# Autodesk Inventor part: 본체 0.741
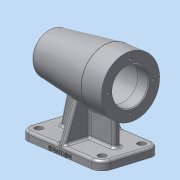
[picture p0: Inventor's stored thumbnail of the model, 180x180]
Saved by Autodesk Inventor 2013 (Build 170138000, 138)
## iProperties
Created: 2018-09
Part Number: 본체 0.741
Material: 알루미늄 6061
Document SubType Name: Modeling
Designer: Administrator
Mass: 734.473 g
Surface Area: 668.157 cm^2
Volume: 271.023 cm^3
Density: 2.71 g/cm^3
Author: Administrator
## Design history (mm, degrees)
sketch "스케치1"
  geometry: L1 (-56, 35)-(56, 35); L2 (56, 35)-(56, -35); L3 (56, -35)-(-56, -35); L4 (-56, -35)-(-56, 35); L5 (-56, 35)-(56, -35); L6 (56, 35)-(-56, -35); 1 further point
  constraints: 12 end point, 2 midpoint, 2 parallel, 1 horizontal, 1 perpendicular
  dimensions: "d0" = 112 distance of L2.end L3.end; "d1" = 70 distance of L1.end L2.end
extrude "돌출1" new body sketch "스케치1" distance "d2" = 10; taper "d3" = 0 deg
sketch "스케치2"
  geometry: L1 (-56, 0)-(56, 0) reference; L2 (-56, 74)-(56, 74); L3 (56, 74)-(56, 108); L4 (56, 108)-(28, 108); L5 (28, 108)-(-52.27, 98.144); A1 r 80 centre (24, 74) between (-52.27, 98.144) and (-56, 74); 1 further point
  constraints: 8 end point, 2 perpendicular, 2 point on circle, 1 centre point, 1 parallel, 1 point on line, 1 vertical alignment
  dimensions: "d4" = 112 distance of L2.start L2.end; "d6" = 74 distance between parallel lines of L1 L2; "d7" = 80 radius of A1; "d8" = 68 diameter of L4 L2; "d9" = 28 distance of L3.end L4.end; "d10" = 7 deg angle of L5 L4
revolve "회전1" sketch "스케치2" stored, may be unused: angle "d11" = 90 deg
sketch "스케치3"
  geometry: L1 (56, 40)-(56, 108) reference; L2 (-56, 74)-(56, 74); L3 (56, 95)-(41, 95); L4 (41, 95)-(41, 98); L5 (41, 98)-(-13, 98); L6 (-13, 98)-(-13, 95); L7 (-13, 95)-(-25, 95); L8 (-25, 95)-(-25, 91.5); L9 (-25, 91.5)-(-43, 91.5); L10 (-43, 91.5)-(-43, 90); L11 (-43, 90)-(-47, 90); L12 (-47, 90)-(-47, 84.5); L13 (-47, 84.5)-(-50, 84.5); L14 (-50, 84.5)-(-50, 74); L15 (56, 95)-(56, 74); A1 r 80 centre (24, 74) between (-52.27, 98.144) and (-52.27, 49.856) reference; 1 further point
  constraints: 28 end point, 10 parallel, 2 perpendicular, 2 point on line, 1 collinear, 1 midpoint, 1 point on circle
  dimensions: "d12" = 42 diameter of L3 L2; "d14" = 48 diameter of L5 L2; "d15" = 42 diameter of L7 L2; "d16" = 35 diameter of L9 L2; "d17" = 32 diameter of L11 L2; "d18" = 21 diameter of L13 L2; "d19" = 15 distance between parallel lines of L1 L4; "d20" = 54 distance between parallel lines of L4 L6; "d21" = 12 distance of L6.end L7.end; "d22" = 18 distance of L8.end L9.end; "d23" = 4 distance between parallel lines of L10 L12; "d24" = 3 distance between parallel lines of L12 L14
revolve "회전2" sketch "스케치3" stored, may be unused: angle "d25" = 90 deg
fillet "모깎기1" dims "d30" = 3
fillet "모깎기2" dims "d31" = 3
fillet "모깎기3" dims "d32" = 3
fillet "모깎기4" dims "d33" = 0.3
chamfer "모따기1" distance "d34" = 1; stored, may be unused: second distance "d35" = 2, angle "d36" = 45 deg
sketch "스케치9"
  geometry: L1 (56, 10)-(56, 0) reference; L2 (56, 0)-(-56, 0) reference; L3 (-56, 0)-(-56, 10) reference; L4 (-56, 10)-(56, 10) reference; L5 (-50.331, 98.382)-(27.818, 107.978) reference; L6 (28.183, 108)-(56, 108) reference; L7 (56, 108)-(56, 96) reference; L8 (56, 96)-(55, 95) reference; L9 (55, 95)-(41, 95) reference; L10 (38, 98)-(-10, 98) reference; L11 (-13, 95)-(-24.7, 95) reference; L12 (-25, 94.7)-(-25, 91.5) reference; L13 (-25, 91.5)-(-42.7, 91.5) reference; L14 (-43, 91.2)-(-43, 90) reference; L15 (-43, 90)-(-46.7, 90) reference; L16 (-47, 89.7)-(-47, 84.5) reference; L17 (-50, 81.5)-(-50, 66.5) reference; L18 (-47, 63.5)-(-47, 58.3) reference; L19 (-46.7, 58)-(-43, 58) reference; L20 (-43, 58)-(-43, 56.8) reference; L21 (-42.7, 56.5)-(-25, 56.5) reference; L22 (-25, 56.5)-(-25, 53.3) reference; L23 (-24.7, 53)-(-13, 53) reference; L24 (-10, 50)-(38, 50) reference; L25 (41, 53)-(55, 53) reference; L26 (55, 53)-(56, 52) reference; L27 (56, 52)-(56, 40) reference; L28 (56, 40)-(28.183, 40) reference; L29 (27.818, 40.022)-(-50.331, 49.618) reference; L30 (-28.115, 46.89)-(-38, 10); L31 (38, 10)-(38, 40); L32 (-38, 10)-(38, 10); A1 r 3 centre (-49.965, 95.405) between (-50.331, 98.382) and (-52.847, 96.238) reference; A2 r 3 centre (28.183, 105) between (28.183, 108) and (27.818, 107.978) reference; A3 r 3 centre (38, 95) between (41, 95) and (38, 98) reference; A4 r 3 centre (-10, 95) between (-10, 98) and (-13, 95) reference; A5 r 0.3 centre (-24.7, 94.7) between (-24.7, 95) and (-25, 94.7) reference; A6 r 0.3 centre (-42.7, 91.2) between (-42.7, 91.5) and (-43, 91.2) reference; A7 r 0.3 centre (-46.7, 89.7) between (-46.7, 90) and (-47, 89.7) reference; A8 r 3 centre (-47, 81.5) between (-47, 84.5) and (-50, 81.5) reference; A9 r 3 centre (-47, 66.5) between (-50, 66.5) and (-47, 63.5) reference; A10 r 0.3 centre (-46.7, 58.3) between (-47, 58.3) and (-46.7, 58) reference; A11 r 0.3 centre (-42.7, 56.8) between (-43, 56.8) and (-42.7, 56.5) reference; A12 r 0.3 centre (-24.7, 53.3) between (-25, 53.3) and (-24.7, 53) reference; A13 r 3 centre (-10, 53) between (-13, 53) and (-10, 50) reference; A14 r 3 centre (38, 53) between (38, 50) and (41, 53) reference; A15 r 3 centre (28.183, 43) between (27.818, 40.022) and (28.183, 40) reference; A16 r 3 centre (-49.965, 52.595) between (-52.847, 51.762) and (-50.331, 49.618) reference; A17 r 80 centre (24, 74) between (-52.847, 96.238) and (-52.847, 51.762) reference; 1 further point
  constraints: 6 end point, 4 point on line, 1 collinear, 1 perpendicular
  dimensions: "d40" = 18 distance between parallel lines of L1 L31; "d41" = 18 distance of L3.end L30.end; "d42" = 105 deg angle of L4 L30
feature "리브1" sketch "스케치9" dims "d43" = 1, "d44" = 8, "d45" = 0, "d46" = 0, "d47" = 1, "d48" = 1
fillet "모깎기6" dims "d57" = 12
fillet "모깎기8" dims "d59" = 3
sketch "스케치11"
  geometry: L1 (100, 0)-(100, 10) reference; 3 further points
  constraints: 1 other
  dimensions: "d63" = 56 distance from line of L1 point (44, 3); "d64" = 3 vertical distance of L1.start point (44, 3)
feature "엠보싱1" sketch "스케치11" dims "d0" = 112, "d1" = 70, "d65" = 0.5, "d66" = 0
sketch "스케치12"
  geometry: C1 r 34 at (0, 0) reference; 2 further points
  constraints: 1 vertical alignment
  dimensions: "d67" = 26 distance of C1.centre point (0, 26)
hole "구멍1" sketch "스케치12" at (0, 26) diameter "d68" = 3.242; stored, may be unused: countersink angle "d72" = 90 deg, drill point angle "d74" = 118 deg; dims "d69" = 8, "d70" = 4, "d71" = 2, "d73" = 11
sketch "스케치13"
  geometry: L1 (56, 23)-(56, -23) reference; L2 (44, -35)-(-44, -35) reference; L3 (-56, -23)-(-56, 23) reference; L4 (-44, 35)-(44, 35) reference; A1 r 12 centre (44, 23) between (56, 23) and (44, 35) reference; A2 r 12 centre (44, -23) between (44, -35) and (56, -23) reference; A3 r 12 centre (-44, -23) between (-56, -23) and (-44, -35) reference; A4 r 12 centre (-44, 23) between (-44, 35) and (-56, 23) reference; 5 further points
  constraints: 4 coincident
hole "구멍2" sketch "스케치13" at (-44, 23), (-44, -23), (44, -23), (44, 23) diameter "d78" = 5.5; stored, may be unused: countersink angle "d82" = 90 deg, drill point angle "d84" = 118 deg; dims "d79" = 6, "d80" = 9.5, "d81" = 5.4, "d83" = 8
fillet "모깎기12" dims "d85" = 3
sketch "스케치15"
  geometry: L1 (4.577, 35)-(4.577, 35.5) reference; L2 (4.577, 35.5)-(4.908, 35.5) reference; L3 (4.908, 35.5)-(4.908, 35) reference; L4 (4.908, 35)-(7, 35) reference; L5 (10, 32)-(10, 4) reference; L6 (10, 4)-(43.701, 4) reference; L7 (43.701, -4)-(10, -4) reference; L8 (10, -4)-(10, -32) reference; L9 (7, -35)-(0, -35) reference; L10 (0, -35)-(0, 35) reference; L11 (0, 35)-(4.577, 35) reference; L12 (50.386, 19.401)-(8.026, 34.819); C1 r 24 at (74, 0) reference; A1 r 3 centre (7, 32) between (10, 32) and (7, 35) reference; A2 r 30.562 centre (74, 0) between (43.701, -4) and (43.701, 4) reference; A3 r 3 centre (7, -32) between (7, -35) and (10, -32) reference; 1 further point
  constraints: 2 end point, 2 point on circle, 1 tangent
  dimensions: "d86" = 20 deg angle of L12 L4
extrude "돌출3" join sketch "스케치15" stored distance "d87" = 8; taper "d88" = 0 deg
fillet "모깎기13" dims "d89" = 3
fillet "모깎기14" dims "d90" = 3
fillet "모깎기15" dims "d91" = 3
fillet "모깎기16" dims "d92" = 3
node "솔리드1"
pattern_circular "원형 패턴1" dims angle "d76" = 360 deg
mirror "대칭2"
node "투영된 루프1"
node "절단 모서리 투영2"
node "절단 모서리 투영4"
